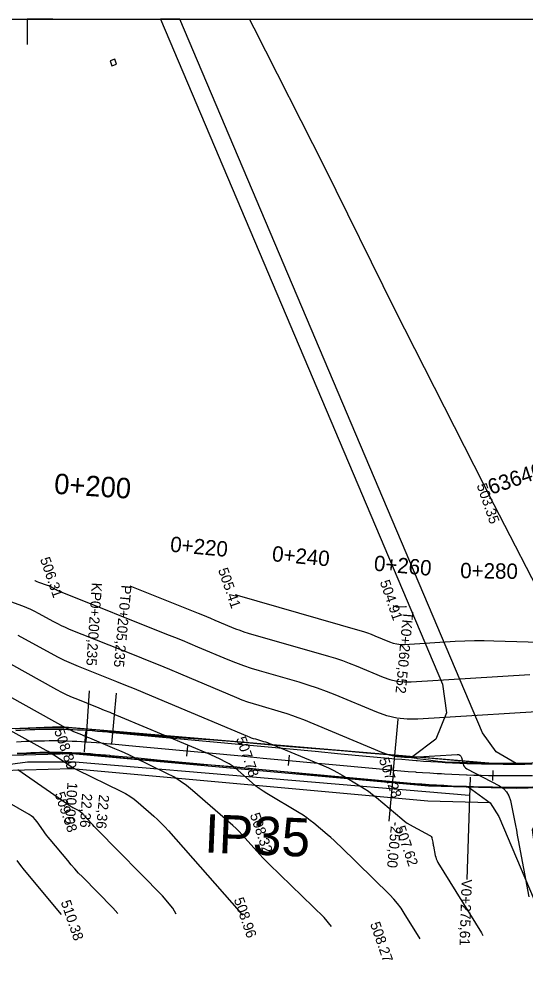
# Model space of a CAD drawing. Extents: x -636600 to -628587, y -1090963 to -1085869.
# Drawn here: x -629638.8 to -629539.8, y -1090852.8 to -1090665.8 of the extents above; entities that cross this region are included whole.
import ezdxf

# ---------------------------------------------------------------- set-up
doc = ezdxf.new("R2010")
doc.units = 0
for name, color, linetype in [('01_PARCELY_NÁVRH_PC', 7, 'Continuous'), ('06_ÚSES_IP_NAVRH', 7, 'Continuous'), ('08_LEGENDA_HV', 7, 'Continuous'), ('42', 7, 'Continuous'), ('52', 7, 'Continuous'), ('Ex_Major Contours', 7, 'Continuous'), ('Ex_Minor Contours', 7, 'Continuous'), ('HEKTOMETRY100', 7, 'Continuous'), ('HEKTOMETRY20', 7, 'Continuous'), ('HL_BODY', 7, 'Continuous'), ('koty_vše', 7, 'Continuous'), ('POLOMERY', 7, 'Continuous'), ('situace_osa', 7, 'Continuous'), ('situace_těleso', 7, 'Continuous'), ('situace_vozovka', 7, 'Continuous'), ('síť křížků', 7, 'Continuous'), ('VRCHOLY', 7, 'Continuous')]:
    doc.layers.add(name, color=color, linetype=linetype)

msp = doc.modelspace()

# ---------------------------------------------------------------- linework, layer by layer
at = {"layer": '01_PARCELY_NÁVRH_PC'}
msp.add_line((-629607.43, -1090665.82), (-629611.23, -1090665.82), dxfattribs=at)
for points in [[(-629611.23, -1090665.82), (-629556.07, -1090795.92), (-629555.31, -1090801.53), (-629557.41, -1090806.63), (-629561.9, -1090810.07), (-629547.05, -1090811.34), (-629541.69, -1090811.43), (-629545.62, -1090809.13), (-629548.24, -1090805.4), (-629607.43, -1090665.82)], [(-629366.45, -1090806.54), (-629540.95, -1090811.44), (-629547.05, -1090811.34), (-629630.75, -1090804.21), (-629643.55, -1090804.77), (-629656.06, -1090806.87), (-629680.19, -1090814.27), (-629692.51, -1090816.32), (-629826.29, -1090824.45), (-629825.42, -1090824.93), (-629821.23, -1090830.23), (-629818.34, -1090839.45), (-629817.55, -1090834.47), (-629814.57, -1090830.54), (-629810, -1090828.44), (-629690.54, -1090821.5), (-629677.85, -1090819.12), (-629655.84, -1090812.08), (-629642.72, -1090809.88), (-629628.47, -1090809.45), (-629558.8, -1090815.77), (-629541.71, -1090816.24), (-629432.05, -1090813.18)], [(-629481.5, -1090962.82), (-629537.74, -1090830.17), (-629538.49, -1090824.4), (-629536.11, -1090819.09), (-629531.76, -1090815.97), (-629541.71, -1090816.24), (-629551.1, -1090815.98), (-629546.74, -1090819.11), (-629545.09, -1090821.81), (-629485.3, -1090962.82)]]:
    msp.add_lwpolyline(points, dxfattribs=at)
msp.add_lwpolyline([(-629815.5, -1090831.76), (-629814.57, -1090830.54), (-629810, -1090828.44), (-629690.54, -1090821.5), (-629677.85, -1090819.12), (-629655.84, -1090812.08), (-629642.72, -1090809.88), (-629628.47, -1090809.45), (-629558.8, -1090815.77), (-629551.1, -1090815.98), (-629546.74, -1090819.11), (-629558.97, -1090818.77), (-629628.56, -1090812.45), (-629642.43, -1090812.87), (-629655.13, -1090815), (-629677.12, -1090822.03), (-629690.18, -1090824.48)], close=True, dxfattribs=at)
at = {"layer": '06_ÚSES_IP_NAVRH'}
msp.add_lwpolyline([(-629809.39, -1090829.88), (-629689.14, -1090823.02), (-629677.01, -1090820.36), (-629655.14, -1090813.49), (-629637.21, -1090811.06), (-629627.89, -1090811.09), (-629550.85, -1090817.6)], dxfattribs=at)
at = {"layer": '08_LEGENDA_HV'}
msp.add_line((-629847.27, -1090665.82), (-629007.27, -1090665.82), dxfattribs=at)
msp.add_lwpolyline([(-629632.27, -1090665.82), (-629637.27, -1090665.82), (-629637.27, -1090670.82)], dxfattribs=at)
at = {"layer": '42'}
for p, q in [((-629592.9, -1090667.62), (-629593.78, -1090665.82)), ((-629579.15, -1090694.72), (-629592.9, -1090667.62)), ((-629565.42, -1090722.64), (-629579.15, -1090694.72)), ((-629545.99, -1090760.83), (-629565.42, -1090722.64)), ((-629526.15, -1090799.4), (-629545.99, -1090760.83))]:
    msp.add_line(p, q, dxfattribs=at)
at = {"layer": '52'}
msp.add_lwpolyline([(-629621.06, -1090673.99), (-629620.74, -1090674.94), (-629619.79, -1090674.61), (-629620.12, -1090673.67)], close=True, dxfattribs=at)
at = {"layer": 'Ex_Major Contours'}
for points in [[(-629565.72, -1090780.52), (-629565.66, -1090780.55), (-629565.23, -1090780.73), (-629565.12, -1090780.76), (-629565.01, -1090780.79), (-629564.89, -1090780.8), (-629564.78, -1090780.8), (-629563.29, -1090780.71), (-629563.12, -1090780.7)], [(-629639.1, -1090786.32), (-629637.79, -1090787.01), (-629632.64, -1090789.86), (-629631.34, -1090790.55), (-629630.02, -1090791.2), (-629628.68, -1090791.81), (-629627.32, -1090792.38), (-629619.79, -1090795.39), (-629618.08, -1090796.07), (-629616.37, -1090796.77), (-629614.67, -1090797.47), (-629612.97, -1090798.18), (-629594.23, -1090806.07), (-629593.85, -1090806.22), (-629593.46, -1090806.37), (-629593.07, -1090806.5), (-629592.67, -1090806.62), (-629591.07, -1090807.08), (-629590.68, -1090807.2), (-629590.28, -1090807.33), (-629589.89, -1090807.48), (-629589.51, -1090807.63), (-629579.31, -1090811.87), (-629578.39, -1090812.28), (-629577.48, -1090812.71), (-629576.59, -1090813.18), (-629575.72, -1090813.68), (-629572.25, -1090815.75), (-629571.4, -1090816.28), (-629570.57, -1090816.85), (-629569.76, -1090817.45), (-629568.98, -1090818.09), (-629564.06, -1090822.25), (-629563.53, -1090822.67), (-629562.98, -1090823.07), (-629562.41, -1090823.43), (-629561.82, -1090823.76), (-629558.56, -1090825.48), (-629558.41, -1090825.58), (-629558.29, -1090825.71), (-629558.2, -1090825.86), (-629558.14, -1090826.04), (-629557.99, -1090826.8), (-629557.95, -1090826.99), (-629557.91, -1090827.18), (-629557.88, -1090827.37), (-629557.84, -1090827.57), (-629557.51, -1090829.38), (-629557.42, -1090829.74), (-629557.31, -1090830.09), (-629557.16, -1090830.42), (-629556.98, -1090830.75), (-629548.43, -1090844.54), (-629548.19, -1090845.06)], [(-629619.57, -1090840.78), (-629620.53, -1090839.63), (-629626.46, -1090833.6), (-629627.21, -1090832.83), (-629627.94, -1090832.04), (-629628.65, -1090831.23), (-629629.35, -1090830.41), (-629632.8, -1090826.26), (-629633.14, -1090825.84), (-629633.47, -1090825.42), (-629633.8, -1090824.99), (-629634.11, -1090824.55), (-629635.35, -1090822.79), (-629635.68, -1090822.37), (-629636.05, -1090821.99), (-629636.46, -1090821.66), (-629636.91, -1090821.37), (-629641.16, -1090818.89)]]:
    msp.add_lwpolyline(points, dxfattribs=at)
at = {"layer": 'Ex_Minor Contours'}
for points in [[(-629531.37, -1090800.91), (-629560.9, -1090802.74), (-629562.97, -1090802.75), (-629565, -1090802.53), (-629566.99, -1090802.08), (-629568.94, -1090801.39), (-629577.04, -1090798.01), (-629578.79, -1090797.32), (-629580.55, -1090796.67), (-629582.33, -1090796.07), (-629584.13, -1090795.53), (-629591.86, -1090793.3), (-629593.41, -1090792.83), (-629594.95, -1090792.31), (-629596.47, -1090791.75), (-629597.97, -1090791.14), (-629603.94, -1090788.63), (-629605.44, -1090788), (-629606.94, -1090787.38), (-629608.44, -1090786.77), (-629609.94, -1090786.17), (-629630.76, -1090777.85), (-629630.98, -1090777.76), (-629631.19, -1090777.66), (-629631.4, -1090777.56), (-629631.61, -1090777.45), (-629632.44, -1090776.99), (-629632.64, -1090776.88), (-629632.86, -1090776.78), (-629633.07, -1090776.69), (-629633.29, -1090776.6), (-629634.99, -1090775.98), (-629635.34, -1090775.85), (-629635.69, -1090775.7), (-629635.77, -1090775.67)], [(-629617.21, -1090776.69), (-629603.85, -1090782.03), (-629603.03, -1090782.36), (-629602.22, -1090782.69), (-629601.41, -1090783.02), (-629600.6, -1090783.36), (-629597.36, -1090784.73), (-629596.54, -1090785.05), (-629595.72, -1090785.36), (-629594.89, -1090785.64), (-629594.05, -1090785.89), (-629578.39, -1090790.4), (-629577.02, -1090790.82), (-629575.66, -1090791.27), (-629574.32, -1090791.77), (-629572.99, -1090792.3), (-629567.7, -1090794.5), (-629566.36, -1090794.97), (-629565, -1090795.28), (-629563.61, -1090795.43), (-629562.2, -1090795.43), (-629538.99, -1090793.99)], [(-629644.38, -1090778.33), (-629638.21, -1090780.59), (-629637.42, -1090780.9), (-629636.64, -1090781.23), (-629635.87, -1090781.6), (-629635.12, -1090782), (-629632.12, -1090783.65), (-629631.37, -1090784.05), (-629630.61, -1090784.43), (-629629.83, -1090784.78), (-629629.04, -1090785.11), (-629616.04, -1090790.31), (-629613.84, -1090791.19), (-629611.66, -1090792.08), (-629609.47, -1090792.98), (-629607.29, -1090793.9), (-629596.34, -1090798.51), (-629595.28, -1090798.94), (-629594.2, -1090799.33), (-629593.11, -1090799.7), (-629592.02, -1090800.03), (-629587.6, -1090801.3), (-629586.5, -1090801.64), (-629585.42, -1090802), (-629584.34, -1090802.4), (-629583.28, -1090802.82), (-629568, -1090809.18), (-629566.54, -1090809.7), (-629565.04, -1090810.04), (-629563.52, -1090810.2), (-629561.96, -1090810.2), (-629553.2, -1090809.65), (-629552.9, -1090809.67), (-629552.67, -1090809.78), (-629552.5, -1090809.97), (-629552.39, -1090810.24), (-629552.07, -1090811.5), (-629551.97, -1090811.79), (-629551.81, -1090812.05), (-629551.6, -1090812.26), (-629551.34, -1090812.43), (-629544.96, -1090815.8), (-629544.17, -1090816.32), (-629543.55, -1090816.97), (-629543.1, -1090817.75), (-629542.82, -1090818.66), (-629542.03, -1090822.54), (-629541.84, -1090823.51), (-629541.65, -1090824.48), (-629541.46, -1090825.46), (-629541.28, -1090826.43), (-629539.24, -1090837.48)], [(-629596.52, -1090778.39), (-629596.49, -1090778.41), (-629596.36, -1090778.45), (-629596.23, -1090778.49), (-629572.24, -1090785.4), (-629571.5, -1090785.62), (-629570.77, -1090785.87), (-629570.04, -1090786.13), (-629569.32, -1090786.42), (-629566.46, -1090787.61), (-629565.74, -1090787.87), (-629565, -1090788.04), (-629564.25, -1090788.12), (-629563.49, -1090788.11), (-629553.64, -1090787.5), (-629551.74, -1090787.41), (-629549.84, -1090787.36), (-629547.94, -1090787.35), (-629546.04, -1090787.39), (-629532.64, -1090787.82)], [(-629560.44, -1090845.7), (-629563.55, -1090840.67), (-629564.18, -1090839.72), (-629564.86, -1090838.81), (-629565.6, -1090837.95), (-629566.38, -1090837.13), (-629576.02, -1090827.67), (-629576.65, -1090827.06), (-629577.29, -1090826.47), (-629577.94, -1090825.89), (-629578.6, -1090825.32), (-629581.25, -1090823.07), (-629581.93, -1090822.53), (-629582.63, -1090822.01), (-629583.34, -1090821.52), (-629584.08, -1090821.06), (-629590.41, -1090817.28), (-629591.17, -1090816.81), (-629591.9, -1090816.3), (-629592.61, -1090815.76), (-629593.29, -1090815.19), (-629596.64, -1090812.27), (-629596.99, -1090811.98), (-629597.37, -1090811.71), (-629597.76, -1090811.47), (-629598.16, -1090811.26), (-629599.83, -1090810.45), (-629600.24, -1090810.25), (-629600.66, -1090810.05), (-629601.09, -1090809.86), (-629601.51, -1090809.68), (-629618.99, -1090802.32), (-629620.04, -1090801.89), (-629621.08, -1090801.45), (-629622.13, -1090801.03), (-629623.18, -1090800.6), (-629627.38, -1090798.92), (-629628.43, -1090798.49), (-629629.46, -1090798.02), (-629630.47, -1090797.52), (-629631.47, -1090796.99), (-629640.47, -1090792.01)], [(-629577.76, -1090843.31), (-629579.21, -1090841.53), (-629589.95, -1090831.11), (-629590.57, -1090830.5), (-629591.18, -1090829.87), (-629591.77, -1090829.24), (-629592.35, -1090828.59), (-629594.63, -1090825.99), (-629595.22, -1090825.34), (-629595.82, -1090824.72), (-629596.44, -1090824.12), (-629597.09, -1090823.54), (-629604.93, -1090816.69), (-629606.11, -1090815.73), (-629607.34, -1090814.85), (-629608.63, -1090814.05), (-629609.98, -1090813.34), (-629616.37, -1090810.23), (-629617.3, -1090809.78), (-629618.23, -1090809.35), (-629619.17, -1090808.93), (-629620.11, -1090808.53), (-629625.02, -1090806.46), (-629625.41, -1090806.3), (-629625.8, -1090806.14), (-629626.18, -1090805.98), (-629626.57, -1090805.82), (-629628.13, -1090805.2), (-629628.52, -1090805.04), (-629628.9, -1090804.86), (-629629.28, -1090804.68), (-629629.65, -1090804.48), (-629643.15, -1090797.02)], [(-629647.79, -1090800.95), (-629633.6, -1090808.79), (-629633.07, -1090809.09), (-629632.56, -1090809.4), (-629632.05, -1090809.72), (-629631.54, -1090810.06), (-629629.55, -1090811.44), (-629629.05, -1090811.77), (-629628.54, -1090812.09), (-629628.01, -1090812.38), (-629627.47, -1090812.66), (-629618.95, -1090816.81), (-629618.06, -1090817.28), (-629617.2, -1090817.81), (-629616.38, -1090818.4), (-629615.6, -1090819.04), (-629612.53, -1090821.71), (-629611.78, -1090822.39), (-629611.05, -1090823.1), (-629610.34, -1090823.83), (-629609.66, -1090824.58), (-629595.86, -1090840.3), (-629595.72, -1090840.47), (-629595.57, -1090840.63), (-629595.42, -1090840.79), (-629595.26, -1090840.95), (-629595.14, -1090841.07)], [(-629608.14, -1090840.91), (-629608.83, -1090839.7), (-629610.82, -1090837.32), (-629623.68, -1090824.26), (-629623.94, -1090823.98), (-629624.2, -1090823.71), (-629624.46, -1090823.42), (-629624.72, -1090823.14), (-629626.05, -1090821.62), (-629626.14, -1090821.52), (-629626.23, -1090821.43), (-629626.33, -1090821.33), (-629626.42, -1090821.24), (-629626.82, -1090820.9), (-629626.93, -1090820.81), (-629627.03, -1090820.74), (-629627.15, -1090820.67), (-629627.26, -1090820.61), (-629628.14, -1090820.18), (-629628.33, -1090820.08), (-629628.51, -1090819.98), (-629628.68, -1090819.87), (-629628.86, -1090819.76), (-629639.1, -1090812.67)], [(-629639.31, -1090830.41), (-629638.59, -1090831.34), (-629637.85, -1090832.25), (-629630.64, -1090840.92)]]:
    msp.add_lwpolyline(points, dxfattribs=at)
at = {"layer": 'HEKTOMETRY100'}
msp.add_lwpolyline([(-629625.84, -1090805.15), (-629626.1, -1090809.14)], dxfattribs=at)
at = {"layer": 'HEKTOMETRY20'}
for points in [[(-629605.96, -1090807.96), (-629606.15, -1090809.95)], [(-629586.05, -1090809.81), (-629586.23, -1090811.8)], [(-629566.13, -1090811.66), (-629566.32, -1090813.65)], [(-629546.25, -1090812.75), (-629546.28, -1090814.75)]]:
    msp.add_lwpolyline(points, dxfattribs=at)
at = {"layer": 'HL_BODY'}
for points in [[(-629625.74, -1090807.16), (-629625.06, -1090797.19)], [(-629620.75, -1090807.59), (-629619.83, -1090797.63)], [(-629565.68, -1090812.71), (-629564.75, -1090802.75)]]:
    msp.add_lwpolyline(points, dxfattribs=at)
at = {"layer": 'POLOMERY'}
for points in [[(-629625.74, -1090807.16), (-629625.06, -1090797.19)], [(-629620.75, -1090807.59), (-629619.83, -1090797.63)], [(-629565.68, -1090812.71), (-629566.6, -1090822.66)]]:
    msp.add_lwpolyline(points, dxfattribs=at)
at = {"layer": 'situace_osa'}
msp.add_lwpolyline([(-629639.36, -1090807.17), (-629638.45, -1090807.11), (-629637.54, -1090807.06), (-629636.63, -1090807.02), (-629635.97, -1090807), (-629635.73, -1090806.99), (-629634.82, -1090806.96), (-629633.91, -1090806.95), (-629633, -1090806.94), (-629632.09, -1090806.94), (-629631.18, -1090806.94), (-629630.97, -1090806.95), (-629630.27, -1090806.96), (-629629.37, -1090806.98), (-629628.46, -1090807.02), (-629627.55, -1090807.06), (-629626.64, -1090807.11), (-629625.97, -1090807.15), (-629625.74, -1090807.16), (-629624.74, -1090807.24), (-629623.74, -1090807.32), (-629622.75, -1090807.4), (-629621.75, -1090807.49), (-629620.99, -1090807.56), (-629620.75, -1090807.59), (-629616.01, -1090808.03), (-629611.03, -1090808.49), (-629606.05, -1090808.95), (-629601.07, -1090809.42), (-629596.1, -1090809.88), (-629591.12, -1090810.34), (-629586.14, -1090810.8), (-629581.16, -1090811.27), (-629576.18, -1090811.73), (-629571.2, -1090812.19), (-629566.22, -1090812.66), (-629565.68, -1090812.71), (-629564.25, -1090812.84), (-629562.82, -1090812.96), (-629561.39, -1090813.07), (-629561.24, -1090813.08), (-629559.97, -1090813.17), (-629558.54, -1090813.27), (-629557.11, -1090813.36), (-629556.25, -1090813.4), (-629555.68, -1090813.44), (-629554.25, -1090813.51), (-629552.82, -1090813.57), (-629551.39, -1090813.62), (-629551.26, -1090813.63), (-629549.96, -1090813.67), (-629548.52, -1090813.71), (-629547.09, -1090813.74), (-629546.26, -1090813.75), (-629545.66, -1090813.76), (-629544.23, -1090813.78), (-629542.8, -1090813.78), (-629541.36, -1090813.78), (-629541.26, -1090813.78), (-629539.93, -1090813.77), (-629538.5, -1090813.75)], dxfattribs=at)
at = {"layer": 'situace_těleso'}
for points in [[(-629639.53, -1090804.63), (-629638.6, -1090804.57), (-629637.67, -1090804.52), (-629636.74, -1090804.47), (-629636.05, -1090804.45), (-629635.81, -1090804.44), (-629634.88, -1090804.41), (-629633.95, -1090804.39), (-629633.01, -1090804.38), (-629632.08, -1090804.37), (-629631.15, -1090804.37), (-629630.93, -1090804.38), (-629630.22, -1090804.39), (-629629.29, -1090804.4), (-629628.35, -1090804.45), (-629627.42, -1090804.51), (-629626.5, -1090804.58), (-629625.81, -1090804.64), (-629625.57, -1090804.66), (-629624.55, -1090804.75), (-629623.54, -1090804.85), (-629622.53, -1090804.95), (-629621.53, -1090805.05), (-629620.76, -1090805.13), (-629620.53, -1090805.16), (-629615.79, -1090805.62), (-629610.8, -1090806.04), (-629605.82, -1090806.43), (-629600.83, -1090806.81), (-629595.85, -1090807.2), (-629590.87, -1090807.64), (-629585.88, -1090808.06), (-629580.9, -1090808.48), (-629575.92, -1090808.9), (-629570.94, -1090809.32), (-629565.95, -1090809.74), (-629565.4, -1090809.78), (-629564, -1090809.98), (-629562.6, -1090810.19), (-629561.19, -1090810.39), (-629561.04, -1090810.41), (-629559.79, -1090810.58), (-629558.38, -1090810.76), (-629556.97, -1090810.94), (-629556.12, -1090811.03), (-629555.55, -1090811.06), (-629554.14, -1090811.13), (-629552.72, -1090811.18), (-629551.3, -1090811.23), (-629551.17, -1090811.24), (-629549.88, -1090811.27), (-629548.47, -1090811.31), (-629547.05, -1090811.34), (-629546.22, -1090811.36), (-629545.63, -1090811.37), (-629544.21, -1090811.4), (-629542.79, -1090811.42), (-629541.38, -1090811.44), (-629541.27, -1090811.44), (-629539.96, -1090811.44), (-629538.54, -1090811.45)], [(-629538.46, -1090816.09), (-629539.91, -1090816.09), (-629541.25, -1090816.08), (-629541.35, -1090816.08), (-629542.8, -1090816.08), (-629544.24, -1090816.09), (-629545.69, -1090816.08), (-629546.29, -1090816.08), (-629547.13, -1090816.07), (-629548.58, -1090816.05), (-629550.03, -1090816.01), (-629551.34, -1090815.98), (-629551.47, -1090815.97), (-629552.91, -1090815.93), (-629554.36, -1090815.87), (-629555.8, -1090815.81), (-629556.38, -1090815.78), (-629557.25, -1090815.73), (-629558.69, -1090815.66), (-629560.13, -1090815.57), (-629561.42, -1090815.48), (-629561.58, -1090815.47), (-629563.02, -1090815.37), (-629564.46, -1090815.26), (-629565.9, -1090815.12), (-629566.45, -1090815.07), (-629571.43, -1090814.58), (-629576.4, -1090814.1), (-629581.38, -1090813.62), (-629586.36, -1090813.14), (-629591.33, -1090812.66), (-629596.31, -1090812.14), (-629601.29, -1090811.77), (-629606.28, -1090811.38), (-629611.26, -1090810.98), (-629616.25, -1090810.56), (-629620.99, -1090810.11), (-629621.22, -1090810.08), (-629621.98, -1090810.01), (-629622.97, -1090809.91), (-629623.95, -1090809.81), (-629624.93, -1090809.72), (-629625.9, -1090809.63), (-629626.13, -1090809.61), (-629626.79, -1090809.56), (-629627.67, -1090809.5), (-629628.56, -1090809.44), (-629629.44, -1090809.42), (-629630.33, -1090809.4), (-629631, -1090809.39), (-629631.22, -1090809.38), (-629632.1, -1090809.38), (-629632.99, -1090809.38), (-629633.87, -1090809.39), (-629634.76, -1090809.4), (-629635.65, -1090809.43), (-629635.88, -1090809.43), (-629636.53, -1090809.46), (-629637.42, -1090809.5), (-629638.3, -1090809.54), (-629639.19, -1090809.59)]]:
    msp.add_lwpolyline(points, dxfattribs=at)
at = {"layer": 'situace_vozovka'}
for points in [[(-629639.51, -1090804.93), (-629638.58, -1090804.87), (-629637.66, -1090804.82), (-629636.73, -1090804.77), (-629636.04, -1090804.75), (-629635.8, -1090804.74), (-629634.87, -1090804.71), (-629633.94, -1090804.7), (-629633.01, -1090804.69), (-629632.08, -1090804.69), (-629631.15, -1090804.69), (-629630.93, -1090804.7), (-629630.22, -1090804.71), (-629629.3, -1090804.74), (-629628.37, -1090804.77), (-629627.44, -1090804.81), (-629626.51, -1090804.86), (-629625.82, -1090804.9), (-629625.58, -1090804.92), (-629624.57, -1090804.99), (-629623.55, -1090805.07), (-629622.55, -1090805.16), (-629621.54, -1090805.25), (-629620.78, -1090805.32), (-629620.55, -1090805.35), (-629615.8, -1090805.79), (-629610.82, -1090806.25), (-629605.84, -1090806.71), (-629600.87, -1090807.18), (-629595.89, -1090807.64), (-629590.91, -1090808.1), (-629585.93, -1090808.56), (-629580.95, -1090809.03), (-629575.97, -1090809.49), (-629570.99, -1090809.95), (-629566.02, -1090810.42), (-629565.47, -1090810.47), (-629564.05, -1090810.59), (-629562.64, -1090810.71), (-629561.22, -1090810.83), (-629561.07, -1090810.84), (-629559.81, -1090810.93), (-629558.39, -1090811.02), (-629556.98, -1090811.11), (-629556.13, -1090811.16), (-629555.56, -1090811.19), (-629554.14, -1090811.26), (-629552.72, -1090811.32), (-629551.31, -1090811.38), (-629551.18, -1090811.38), (-629549.89, -1090811.42), (-629548.47, -1090811.46), (-629547.05, -1090811.49), (-629546.23, -1090811.5), (-629545.63, -1090811.51), (-629544.21, -1090811.53), (-629542.79, -1090811.53), (-629541.38, -1090811.53), (-629541.27, -1090811.53), (-629539.96, -1090811.52), (-629538.54, -1090811.5)], [(-629639.2, -1090809.41), (-629638.32, -1090809.36), (-629637.43, -1090809.31), (-629636.54, -1090809.27), (-629635.89, -1090809.24), (-629635.65, -1090809.24), (-629634.77, -1090809.21), (-629633.88, -1090809.19), (-629632.99, -1090809.19), (-629632.1, -1090809.19), (-629631.21, -1090809.19), (-629631, -1090809.2), (-629630.33, -1090809.21), (-629629.44, -1090809.23), (-629628.55, -1090809.27), (-629627.66, -1090809.31), (-629626.78, -1090809.35), (-629626.12, -1090809.39), (-629625.89, -1090809.41), (-629624.91, -1090809.48), (-629623.93, -1090809.56), (-629622.95, -1090809.64), (-629621.96, -1090809.73), (-629621.2, -1090809.8), (-629620.96, -1090809.83), (-629616.22, -1090810.27), (-629611.24, -1090810.73), (-629606.26, -1090811.19), (-629601.28, -1090811.66), (-629596.3, -1090812.12), (-629591.33, -1090812.58), (-629586.35, -1090813.05), (-629581.37, -1090813.51), (-629576.39, -1090813.97), (-629571.41, -1090814.43), (-629566.43, -1090814.9), (-629565.88, -1090814.95), (-629564.44, -1090815.08), (-629563, -1090815.2), (-629561.56, -1090815.31), (-629561.41, -1090815.32), (-629560.12, -1090815.42), (-629558.68, -1090815.51), (-629557.24, -1090815.6), (-629556.38, -1090815.65), (-629555.8, -1090815.68), (-629554.35, -1090815.75), (-629552.91, -1090815.82), (-629551.47, -1090815.87), (-629551.34, -1090815.88), (-629550.02, -1090815.92), (-629548.58, -1090815.96), (-629547.13, -1090815.99), (-629546.29, -1090816), (-629545.69, -1090816.01), (-629544.24, -1090816.03), (-629542.8, -1090816.03), (-629541.35, -1090816.03), (-629541.25, -1090816.03), (-629539.91, -1090816.02), (-629538.46, -1090816)]]:
    msp.add_lwpolyline(points, dxfattribs=at)
at = {"layer": 'VRCHOLY'}
msp.add_lwpolyline([(-629550.69, -1090814.1), (-629551.34, -1090834.09)], dxfattribs=at)

# ---------------------------------------------------------------- texts
at = {"layer": '06_ÚSES_IP_NAVRH'}
msp.add_text('IP35', height=7.5, rotation=357.5514, dxfattribs=at).set_placement((-629602.72, -1090828.8))
at = {"layer": 'HEKTOMETRY100'}
msp.add_text('0+200', height=4, rotation=356.2543, dxfattribs=at).set_placement((-629632.09, -1090758.65))
at = {"layer": 'HEKTOMETRY20'}
for s, rotation, p in [('0+220', 354.6874, (-629609.41, -1090769.97)), ('0+240', 354.6874, (-629589.5, -1090771.83)), ('0+260', 354.6874, (-629569.59, -1090773.68)), ('0+280', 359.1446, (-629552.64, -1090775.15))]:
    msp.add_text(s, height=3, rotation=rotation, dxfattribs=at).set_placement(p)
at = {"layer": 'HL_BODY'}
for s, rotation, p in [('KP0+200,235', 266.1198, (-629624.62, -1090775.99)), ('PT0+205,235', 264.6874, (-629618.86, -1090776.45)), ('TK0+260,552', 264.6874, (-629563.78, -1090781.57))]:
    msp.add_text(s, height=2, rotation=rotation, dxfattribs=at).set_placement(p)
at = {"layer": 'koty_vše'}
for s, p in [('503.35', (-629549.43, -1090757.01)), ('506.31', (-629634.79, -1090771.44)), ('505.41', (-629599.99, -1090773.53)), ('504.91', (-629568.37, -1090775.9)), ('508.80', (-629632.04, -1090805)), ('507.78', (-629596.47, -1090806.53)), ('507.28', (-629568.55, -1090810.65)), ('509.58', (-629631.94, -1090817.35)), ('508.32', (-629593.77, -1090821.45)), ('507.62', (-629565.34, -1090823.97)), ('510.38', (-629630.74, -1090838.52)), ('508.96', (-629596.91, -1090838)), ('508.27', (-629570.27, -1090842.77))]:
    msp.add_text(s, height=2, rotation=289.043, dxfattribs=at).set_placement(p)
at = {"layer": 'POLOMERY'}
for s, rotation, p in [('100,00', 266.1198, (-629629.39, -1090815.04)), ('22,36', 266.1198, (-629626.53, -1090817.22)), ('22,36', 264.6874, (-629623.2, -1090817.43)), ('-250,00', 264.6874, (-629566.1, -1090822.71))]:
    msp.add_text(s, height=2, rotation=rotation, dxfattribs=at).set_placement(p)
at = {"layer": 'síť křížků'}
msp.add_text('636400', height=3, rotation=19.043, dxfattribs=at).set_placement((-629546.61, -1090758.88))
at = {"layer": 'VRCHOLY'}
msp.add_text('V0+275,61', height=2, rotation=268.1334, dxfattribs=at).set_placement((-629552.34, -1090834.06))

doc.saveas('drawing.dxf')
